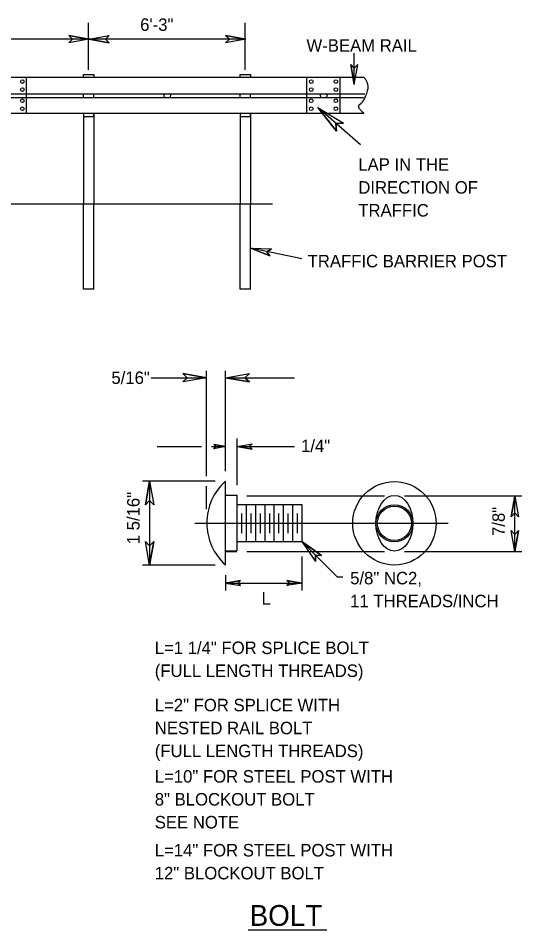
# Model space of a CAD drawing. Extents: x 12.4 to 19.6, y 6 to 16.1.
# Drawn here: x 16.991 to 19.412, y 11.454 to 15.832 of the extents above; entities that cross this region are included whole.
import ezdxf

# ---------------------------------------------------------------- set-up
doc = ezdxf.new("R2010")
doc.units = 0
for name, color, linetype in [('DETL-DIMS', 7, 'Continuous'), ('DETL-LINE', 7, 'Continuous'), ('DETL-NOTE', 7, 'Continuous'), ('DETL-PATT', 7, 'Continuous'), ('DETL-TITL', 7, 'Continuous')]:
    doc.layers.add(name, color=color, linetype=linetype)

msp = doc.modelspace()

# ---------------------------------------------------------------- linework, layer by layer
at = {"layer": 'DETL-DIMS'}
for p, q in [((17.3292, 15.5844), (17.3292, 15.8102)), ((18.0827, 15.5844), (18.0827, 15.8102)), ((17.3312, 15.7313), (16.5776, 15.7313)), ((17.3312, 15.7313), (17.234, 15.7484)), ((17.234, 15.7484), (17.2523, 15.7313)), ((17.3312, 15.7313), (17.234, 15.7141)), ((17.2523, 15.7313), (17.234, 15.7141)), ((17.3312, 15.7313), (17.4285, 15.7484)), ((18.0848, 15.7313), (17.3312, 15.7313)), ((17.3312, 15.7313), (17.4285, 15.7141)), ((17.4101, 15.7313), (17.4285, 15.7484)), ((17.4285, 15.7141), (17.4101, 15.7313)), ((18.0848, 15.7313), (17.9876, 15.7484)), ((17.9876, 15.7484), (18.0059, 15.7313)), ((18.0848, 15.7313), (17.9876, 15.7141)), ((18.0059, 15.7313), (17.9876, 15.7141)), ((18.6066, 15.5129), (18.6066, 15.6636)), ((18.6066, 15.5129), (18.5894, 15.6102)), ((18.5894, 15.6102), (18.6066, 15.5918)), ((18.6066, 15.5129), (18.6237, 15.6102)), ((18.6066, 15.5918), (18.6237, 15.6102)), ((17.0315, 15.376), (17.0315, 15.5482)), ((18.3789, 15.376), (18.3789, 15.5482)), ((18.5387, 15.376), (18.5387, 15.5482)), ((18.4305, 15.4033), (18.5215, 15.2901)), ((18.4305, 15.4033), (18.5547, 15.3281)), ((18.6357, 15.2238), (18.4305, 15.4033)), ((18.5179, 15.3269), (18.5547, 15.3281)), ((18.5215, 15.2901), (18.5179, 15.3269)), ((18.3538, 14.6755), (18.1096, 14.7271)), ((18.1096, 14.7271), (18.2011, 14.6902)), ((18.1096, 14.7271), (18.2082, 14.7237)), ((18.1867, 14.7107), (18.2082, 14.7237)), ((18.2011, 14.6902), (18.1867, 14.7107)), ((17.6296, 14.1052), (17.8967, 14.1052)), ((17.8967, 14.1052), (17.7823, 14.1254)), ((17.7823, 14.1254), (17.8039, 14.1052)), ((17.8967, 14.1052), (17.7823, 14.085)), ((17.8039, 14.1052), (17.7823, 14.085)), ((17.8967, 13.6325), (17.8967, 14.1388)), ((17.9881, 13.6559), (17.9881, 14.1388)), ((17.9881, 14.1052), (18.1025, 14.1254)), ((17.9881, 14.1052), (18.3198, 14.1052)), ((17.9881, 14.1052), (18.1025, 14.085)), ((18.0809, 14.1052), (18.1025, 14.1254)), ((18.1025, 14.085), (18.0809, 14.1052)), ((18.0438, 13.5891), (18.0438, 13.8129)), ((17.6589, 13.7745), (17.8727, 13.7745)), ((17.9207, 13.7745), (17.9881, 13.7745)), ((17.9881, 13.7745), (17.9309, 13.7846)), ((17.9309, 13.7846), (17.9417, 13.7745)), ((17.9881, 13.7745), (17.9309, 13.7644)), ((17.9417, 13.7745), (17.9309, 13.7644)), ((18.0438, 13.7745), (18.1153, 13.7871)), ((18.0438, 13.7745), (18.3198, 13.7745)), ((18.0438, 13.7745), (18.1153, 13.7619)), ((18.1018, 13.7745), (18.1153, 13.7871)), ((18.1153, 13.7619), (18.1018, 13.7745)), ((17.9385, 13.6085), (17.5889, 13.6085)), ((17.6225, 13.6085), (17.6023, 13.4941)), ((17.6225, 13.6085), (17.6225, 13.2049)), ((17.6225, 13.6085), (17.6427, 13.4941)), ((17.8967, 13.4747), (17.8967, 13.5845)), ((18.0895, 13.5377), (18.7515, 13.5377)), ((18.8475, 13.5377), (19.4116, 13.5377)), ((19.378, 13.5372), (19.3604, 13.4371)), ((19.378, 13.2708), (19.378, 13.5372)), ((19.378, 13.5372), (19.3956, 13.4371)), ((17.6023, 13.4941), (17.6225, 13.5157)), ((17.6225, 13.5157), (17.6427, 13.4941)), ((19.3604, 13.4371), (19.378, 13.456)), ((19.378, 13.456), (19.3956, 13.4371)), ((17.8399, 13.4062), (19.0575, 13.4062)), ((19.378, 13.2708), (19.3604, 13.3709)), ((19.378, 13.352), (19.3604, 13.3709)), ((19.378, 13.2708), (19.3956, 13.3709)), ((19.3956, 13.3709), (19.378, 13.352)), ((17.6225, 13.2049), (17.6023, 13.3193)), ((17.6225, 13.2977), (17.6023, 13.3193)), ((17.6225, 13.2049), (17.6427, 13.3193)), ((17.6427, 13.3193), (17.6225, 13.2977)), ((18.354, 13.3184), (18.4491, 13.2518)), ((18.354, 13.3184), (18.4206, 13.2233)), ((18.354, 13.3184), (18.5234, 13.1491)), ((18.0895, 13.2708), (18.7515, 13.2708)), ((18.8475, 13.2708), (19.4116, 13.2708)), ((18.354, 13.2465), (18.354, 13.0829)), ((18.4491, 13.2518), (18.4196, 13.2528)), ((18.4196, 13.2528), (18.4206, 13.2233)), ((17.9385, 13.2049), (17.5889, 13.2049)), ((17.9881, 13.1565), (17.9881, 13.0829)), ((18.5234, 13.1491), (18.5514, 13.1491)), ((17.9881, 13.1194), (18.0596, 13.132)), ((17.9881, 13.1194), (18.354, 13.1194)), ((17.9881, 13.1194), (18.0596, 13.1068)), ((18.0596, 13.132), (18.0461, 13.1194)), ((18.0461, 13.1194), (18.0596, 13.1068)), ((18.354, 13.1194), (18.2825, 13.132)), ((18.2825, 13.132), (18.296, 13.1194)), ((18.354, 13.1194), (18.2825, 13.1068)), ((18.296, 13.1194), (18.2825, 13.1068))]:
    msp.add_line(p, q, dxfattribs=at)
for points in [[(17.234, 15.7484), (17.3312, 15.7313), (17.234, 15.7141), (17.2523, 15.7313)], [(17.4285, 15.7141), (17.3312, 15.7313), (17.4285, 15.7484), (17.4101, 15.7313)], [(17.9876, 15.7484), (18.0848, 15.7313), (17.9876, 15.7141), (18.0059, 15.7313)], [(18.5894, 15.6102), (18.6066, 15.5129), (18.6237, 15.6102), (18.6066, 15.5918)], [(18.5215, 15.2901), (18.4305, 15.4033), (18.5547, 15.3281), (18.5179, 15.3269)], [(18.2011, 14.6902), (18.1096, 14.7271), (18.2082, 14.7237), (18.1867, 14.7107)], [(17.7823, 14.1254), (17.8967, 14.1052), (17.7823, 14.085), (17.8039, 14.1052)], [(18.1025, 14.085), (17.9881, 14.1052), (18.1025, 14.1254), (18.0809, 14.1052)], [(17.9309, 13.7846), (17.9881, 13.7745), (17.9309, 13.7644), (17.9417, 13.7745)], [(18.1153, 13.7619), (18.0438, 13.7745), (18.1153, 13.7871), (18.1018, 13.7745)], [(17.6023, 13.4941), (17.6225, 13.6085), (17.6427, 13.4941), (17.6225, 13.5157)], [(19.3604, 13.4371), (19.378, 13.5372), (19.3956, 13.4371), (19.378, 13.456)], [(19.3956, 13.3709), (19.378, 13.2708), (19.3604, 13.3709), (19.378, 13.352)], [(17.6427, 13.3193), (17.6225, 13.2049), (17.6023, 13.3193), (17.6225, 13.2977)], [(18.4491, 13.2518), (18.354, 13.3184), (18.4206, 13.2233), (18.4196, 13.2528)], [(18.0596, 13.132), (17.9881, 13.1194), (18.0596, 13.1068), (18.0461, 13.1194)], [(18.2825, 13.132), (18.354, 13.1194), (18.2825, 13.1068), (18.296, 13.1194)]]:
    msp.add_lwpolyline(points, close=True, dxfattribs=at)
at = {"layer": 'DETL-LINE'}
for p, q in [((13.5526, 15.5482), (18.6517, 15.5482)), ((17.3043, 15.5612), (17.3542, 15.5612)), ((17.3043, 15.5482), (17.3043, 15.5612)), ((17.3542, 15.5612), (17.3542, 15.5482)), ((18.0574, 15.5612), (18.1073, 15.5612)), ((18.0574, 15.5482), (18.0574, 15.5612)), ((18.1073, 15.5612), (18.1073, 15.5482)), ((13.5475, 15.4682), (18.6567, 15.4682)), ((17.3043, 15.4518), (17.3043, 15.4682)), ((17.3542, 15.4518), (17.3542, 15.4682)), ((17.6985, 15.4688), (17.7162, 15.4688)), ((18.0574, 15.4518), (18.0574, 15.4682)), ((18.1073, 15.4518), (18.1073, 15.4682)), ((18.4507, 15.4688), (18.4684, 15.4688)), ((13.5528, 15.4518), (18.6515, 15.4518)), ((17.6985, 15.4511), (17.7162, 15.4511)), ((18.4507, 15.4511), (18.4684, 15.4511)), ((13.5526, 15.376), (18.6516, 15.376)), ((17.3043, 15.376), (17.3043, 14.9412)), ((17.3043, 15.3726), (17.3043, 15.3596)), ((17.3542, 15.376), (17.3542, 14.9412)), ((17.3542, 15.3596), (17.3542, 15.3726)), ((18.0574, 15.376), (18.0574, 14.9412)), ((18.0574, 15.3726), (18.0574, 15.3596)), ((18.1073, 15.376), (18.1073, 14.9412)), ((18.1073, 15.3596), (18.1073, 15.3726)), ((17.3043, 15.3596), (17.3542, 15.3596)), ((18.0574, 15.3596), (18.1073, 15.3596)), ((13.546, 14.9412), (18.213, 14.9412)), ((17.3043, 14.5311), (17.3043, 14.9412)), ((17.3542, 14.5311), (17.3542, 14.9412)), ((18.0574, 14.5311), (18.0574, 14.9412)), ((18.1073, 14.5311), (18.1073, 14.9412)), ((17.3542, 14.5311), (17.3043, 14.5311)), ((18.1073, 14.5311), (18.0574, 14.5311)), ((17.9865, 13.6079), (17.9865, 13.2045)), ((17.9865, 13.5411), (18.0422, 13.5411)), ((18.0422, 13.5411), (18.0422, 13.2738)), ((18.0422, 13.4965), (18.354, 13.4965)), ((18.0868, 13.4965), (18.0868, 13.3184)), ((18.1313, 13.4965), (18.1313, 13.3184)), ((18.1759, 13.4965), (18.1759, 13.3184)), ((18.2204, 13.4965), (18.2204, 13.3184)), ((18.2649, 13.4965), (18.2649, 13.3184)), ((18.3095, 13.4965), (18.3095, 13.3184)), ((18.354, 13.4965), (18.354, 13.3184)), ((18.0422, 13.3184), (18.354, 13.3184)), ((17.9865, 13.2738), (18.0422, 13.2738)), ((17.9865, 13.2713), (18.0422, 13.2713))]:
    msp.add_line(p, q, dxfattribs=at)
for centre, radius in [((17.0108, 15.5274), 0.00883), ((17.0108, 15.489), 0.00883), ((18.3996, 15.5274), 0.00883), ((18.3996, 15.489), 0.00883), ((18.5179, 15.5274), 0.00883), ((18.5179, 15.489), 0.00883), ((17.0108, 15.4352), 0.00883), ((18.3996, 15.4352), 0.00883), ((18.5179, 15.4352), 0.00883), ((17.0108, 15.3968), 0.00883), ((18.3996, 15.3968), 0.00883), ((18.5179, 15.3968), 0.00883), ((18.7995, 13.4062), 0.2004), ((18.7995, 13.4062), 0.0891), ((18.7995, 13.4062), 0.0823)]:
    msp.add_circle(centre, radius, dxfattribs=at)
for centre, radius, start, end in [((17.6985, 15.46), 0.00883, 90, 270), ((17.7162, 15.46), 0.00883, 270, 90), ((18.4507, 15.46), 0.00883, 90, 270), ((18.4684, 15.46), 0.00883, 270, 90), ((18.1675, 13.4075), 0.27, 132.0737, 227.9263)]:
    msp.add_arc(centre, radius, start, end, dxfattribs=at)
msp.add_ellipse((18.7995, 13.4062), major_axis=(0, -0.1339), ratio=0.665551, dxfattribs=at)
msp.add_open_spline([(18.6516, 15.376), (18.6153, 15.4071), (18.6524, 15.4303), (18.6834, 15.5165), (18.6516, 15.5482)], degree=2, dxfattribs=at)
at = {"layer": 'DETL-PATT'}
for p, q in [((18.0645, 13.4532), (18.0645, 13.3594)), ((18.109, 13.4532), (18.109, 13.3594)), ((18.1536, 13.4532), (18.1536, 13.3594)), ((18.1981, 13.4532), (18.1981, 13.3594)), ((18.2427, 13.4532), (18.2427, 13.3594)), ((18.2872, 13.4532), (18.2872, 13.3594)), ((18.3318, 13.4532), (18.3318, 13.3594))]:
    msp.add_line(p, q, dxfattribs=at)
at = {"layer": 'DETL-TITL'}
msp.add_line((18.097, 11.4541), (18.4741, 11.4541), dxfattribs=at)

# ---------------------------------------------------------------- texts
at = {"layer": 'DETL-NOTE'}
for s, p in [('6\'-3"', (17.5772, 15.7709)), ('W-BEAM RAIL', (18.3767, 15.671)), ('LAP IN THE', (18.6258, 15.0994)), ('DIRECTION OF ', (18.6258, 14.9894)), ('TRAFFIC', (18.6258, 14.8794)), ('TRAFFIC BARRIER POST', (18.3822, 14.6355)), ('5/16"', (17.439, 14.0752)), ('1/4" ', (18.3508, 13.7483)), ('5/8" NC2,', (18.5866, 13.113)), ('L', (18.1604, 13.0158)), ('11 THREADS/INCH', (18.5866, 13.003)), ('L=1 1/4" FOR SPLICE BOLT', (17.6474, 12.7783)), ('(FULL LENGTH THREADS) ', (17.6474, 12.6683)), ('L=2" FOR SPLICE WITH ', (17.6474, 12.5033)), ('NESTED RAIL BOLT', (17.6474, 12.3933)), ('(FULL LENGTH THREADS)', (17.6474, 12.2833)), ('L=10" FOR STEEL POST WITH', (17.6474, 12.1608)), ('8" BLOCKOUT BOLT', (17.6474, 12.0508)), ('SEE NOTE ', (17.6474, 11.9408)), ('L=14" FOR STEEL POST WITH', (17.6474, 11.8062)), ('12" BLOCKOUT BOLT', (17.6474, 11.6962))]:
    msp.add_text(s, height=0.06, dxfattribs=at).set_placement(p)
for s, p in [('1 5/16"', (17.5745, 13.3054)), ('7/8"', (19.33, 13.3453))]:
    msp.add_text(s, height=0.06, rotation=90, dxfattribs=at).set_placement(p)
at = {"layer": 'DETL-TITL'}
msp.add_text('BOLT', height=0.1, dxfattribs=at).set_placement((18.1034, 11.473))

doc.saveas('drawing.dxf')
